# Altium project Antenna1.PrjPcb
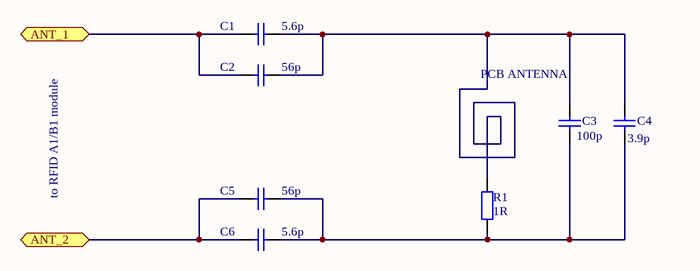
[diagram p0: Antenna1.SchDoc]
1 sheet, 7 parts. Net scope: flat (ports and power ports of the same name join across sheets).

## Sheet Antenna1.SchDoc
size A4

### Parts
C1  5.6p  [0603_CAP]
C2  56p  [0603_CAP]
C3  100p  [0603_CAP]
C4  3.9p  [0603_CAP]
C5  56p  [0603_CAP]
C6  5.6p  [0603_CAP]
R1  1R  [0603_RES]

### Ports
ANT_1, ANT_2

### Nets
NetC1_1: C1.1 C2.2 C3.2 C4.2 R1.2
NetC1_2: C1.2 C2.1 ; port ANT_1
NetC3_1: C3.1 C4.1 C5.2 C6.1 R1.1
NetC5_1: C5.1 C6.2 ; port ANT_2

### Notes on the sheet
- PCB ANTENNA
- to RFID A1/B1 module

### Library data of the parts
C1-C6 = Cap: Capacitor; Is Mounted: no
R1 = Res2: Resistor; Is Mounted: no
